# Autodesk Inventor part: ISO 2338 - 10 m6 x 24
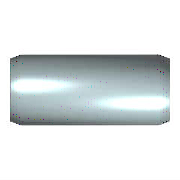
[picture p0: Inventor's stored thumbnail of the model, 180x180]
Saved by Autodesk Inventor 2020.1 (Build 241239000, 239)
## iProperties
Created: 2019-01
Part Number: ISO 2338 - 10 m6 x 24
Material: Edelstahl, austenitisch
Description: Zylinderstift
Document SubType Name: Modeling
Standard: ISO 2338
Designer: lutzd
Standard Revision: Second edition 1997-11-01
Standards Organization: ISO
Language: de-DE
Size Designation: 10 m6 x 24
Categories: <MemberInstance><Categories><Category DisplayName="Verbindungselemente" InternalName="e4da775c-781d-43d5-af7c-5136215cf5a6" Mnemonic="FSTN"><Category DisplayNam
Mass: 14.8199 g
Surface Area: 8.76656 cm^2
Volume: 1.85249 cm^3
Density: 8 g/cm^3
Appearance: Halbpoliert
IsCustomPart: 0
Author: lutzd
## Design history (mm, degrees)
sketch "Skizze"
  geometry: C1 r 5 at (0, 0); 1 further point
  constraints: 1 centre point, 1 coincident
  dimensions: "d1" = 10 diameter of C1 (= NND)
extrude "Körper" new body sketch "Skizze" distance "d2" = 24 (= NLG); taper "d3" = 0 deg
chamfer "Skizze2" distance "d8" = 2 (= PHH); stored, may be unused: angle "d9" = 15 deg (= FAWI), second distance "d12" = 2 (= PHH)
body "Solid1"
chamfer "Fase1" distance "d4" = 2 (= PHH); stored, may be unused: angle "d5" = 15 deg (= FAWI), second distance "d11" = 2 (= PHH)
other parameters: "NND" = 10 [user parameter; used in 1 equation term], "NLG" = 24 [user parameter; used in 1 equation term], "PHH" = 2 [user parameter; used in 4 equation terms], "FAWI" = 15 deg [user parameter; used in 2 equation terms], "d13" = 0, "d15" = 0, "d16" = 0, "KAH" = 0 [user parameter]
